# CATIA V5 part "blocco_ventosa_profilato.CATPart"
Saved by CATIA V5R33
Part number: blocco_ventosa_profilato
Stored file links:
  C:\Users\Ryzen5700u\Desktop\robot_cicloidale_singolo\Assieme_robot_cicloidale_singolo\blocco_ventosa_profilato.CATPart

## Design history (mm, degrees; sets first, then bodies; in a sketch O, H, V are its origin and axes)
Body1 "Solido1" (main body)
  Solid1: solid without history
